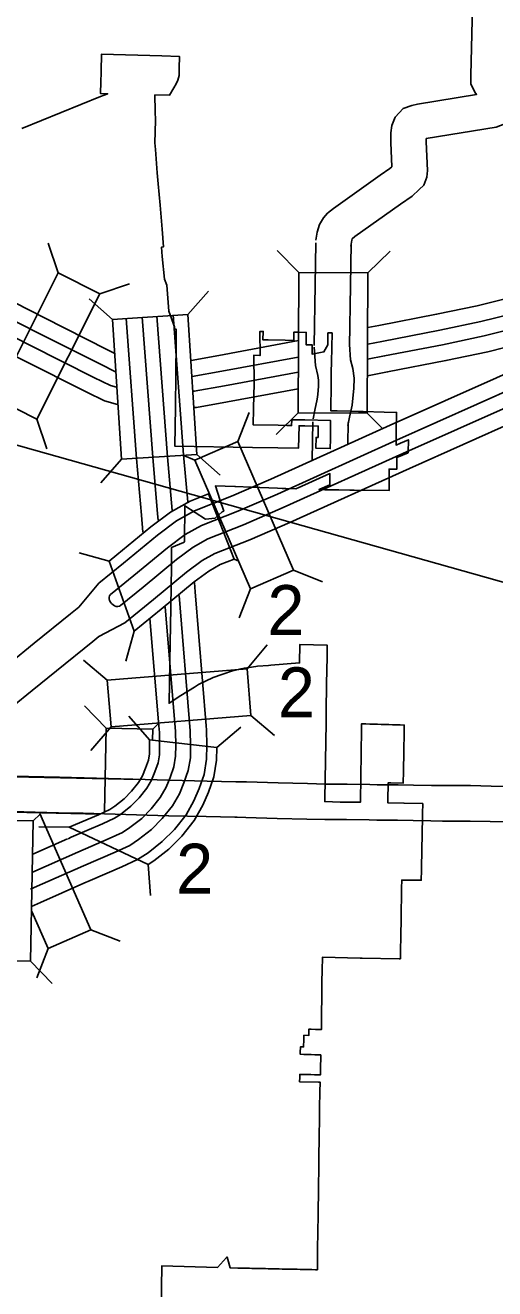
# Model space of a CAD drawing. Extents: x 535214 to 694517, y 381272 to 484355.
# Drawn here: x 547771 to 549760, y 458296 to 463649 of the extents above; entities that cross this region are included whole.
import ezdxf

# ---------------------------------------------------------------- set-up
doc = ezdxf.new("R2010")
doc.units = 0
for name, color, linetype in [('1', 7, 'Continuous'), ('Level 10', 7, 'Continuous'), ('Level 11', 7, 'Continuous'), ('Level 15', 7, 'Continuous'), ('Level 19', 7, 'Continuous'), ('Level 20', 7, 'Continuous'), ('Level 6', 7, 'Continuous')]:
    doc.layers.add(name, color=color, linetype=linetype)

msp = doc.modelspace()

# ---------------------------------------------------------------- linework, layer by layer
at = {"layer": '1'}
msp.add_line((546782.5, 462138.9), (567784.7, 456216.2), dxfattribs=at)
at = {"layer": 'Level 10'}
for p, q in [((548382.3, 460450.2), (548019.6, 460460.4)), ((548378.1, 460300.3), (548015.4, 460310.4))]:
    msp.add_line(p, q, dxfattribs=at)
for points in [[(548994.2, 462291.6), (548998.3, 462549)], [(549144.2, 462289.2), (549148.3, 462546.6)], [(548990.3, 461981.8), (548997.4, 462018.5), (549007.4, 462064.3), (549009.7, 462084), (549012.6, 462119.6), (549013.6, 462145.8), (549010.9, 462165.1), (549000, 462207.5), (548994.4, 462285)], [(549137.6, 461953.5), (549144.3, 461988.3), (549155.5, 462039.6), (549158.9, 462069.1), (549162.4, 462110.6), (549164, 462153.5), (549158.3, 462194.2), (549148.7, 462231.8), (549144, 462295.9)], [(548989, 461968.9), (548986.4, 461806.4)], [(549139, 461966.5), (549137.5, 461875.6)], [(548019.3, 460460.4), (547915, 460462.9), (547717.7, 460467.9), (547627.7, 460469.3), (547565.2, 460470.2), (547553.5, 460470.4), (547486.8, 460471.9), (547444.2, 460472.9), (547418.4, 460473.9), (547374, 460475.4), (547234.3, 460480.4), (547164.2, 460482.9), (547156.4, 460483.1), (547157.8, 460482.7)], [(547369.6, 460471.9), (547718.3, 460464.4), (548256.7, 460454.1)], [(549866.8, 460423.1), (549744.3, 460425.7), (549657.1, 460427.6), (549595.8, 460427.6), (549540.6, 460427.7), (549538.8, 460427.6), (549492, 460428.8), (549415.8, 460429.8), (549350.3, 460431), (549304, 460431.4), (549261.8, 460431.6), (549231, 460432.1), (549134.4, 460434), (549124.3, 460434.2), (549042.2, 460434.5), (548967.1, 460436.1), (548841.8, 460438.9), (548708.6, 460443), (548672.7, 460443.6), (548663.4, 460444), (548540.9, 460446.6), (548381.9, 460450.2)], [(548015.7, 460310.4), (547911.3, 460312.9), (547714.6, 460317.9), (547625.4, 460319.3), (547562.9, 460320.2), (547550.7, 460320.4), (547483.4, 460321.9), (547439.6, 460322.9), (547412.9, 460324), (547368.8, 460325.5), (547229, 460330.5), (547159.1, 460332.9), (547129.5, 460333.9), (547110.1, 460340.4)], [(547126.6, 460327.1), (547715.2, 460314.5), (548088.5, 460307.3)], [(549863, 460273.2), (549741.1, 460275.8), (549655.4, 460277.6), (549595.8, 460277.6), (549542.1, 460277.7), (549538.4, 460277.6), (549489.1, 460278.9), (549413.5, 460279.8), (549348.3, 460281), (549303, 460281.4), (549260.3, 460281.6), (549228.4, 460282.1), (549131.7, 460284.1), (549122.8, 460284.2), (549040.2, 460284.5), (548963.8, 460286.2), (548837.8, 460289), (548705.1, 460293.1), (548668.5, 460293.7), (548658.8, 460294.1), (548537.6, 460296.7), (548378.5, 460300.3)]]:
    msp.add_lwpolyline(points, dxfattribs=at)
at = {"layer": 'Level 11'}
for points in [[(549002.3, 462738.5), (549007.9, 462771.9), (549017, 462804.1), (549034.3, 462833.5), (549050.6, 462852.3), (549076.5, 462873.1), (549274.5, 463013.4), (549316, 463042.7), (549323.9, 463049.8), (549319.7, 463152.2), (549320, 463193.6), (549323.6, 463224.1), (549338.2, 463259.5), (549372.3, 463295.6), (549408.1, 463308.6), (549433.2, 463314.9), (549683, 463356), (549675.8, 463366), (549658.2, 463400.8), (549658.9, 463437.2), (549683.6, 464485.7)], [(549150.1, 462713.3), (549154.5, 462738.9), (549156.1, 462744.6), (549166.9, 462753.3), (549361.1, 462890.9), (549409.9, 462925.3), (549440.3, 462952.9), (549459.9, 462971), (549471.9, 463005.8), (549474.6, 463034.2), (549469.7, 463154.7), (549469.8, 463168.9), (549765.4, 463217.5), (549802.7, 463231.1), (549836.7, 463251.6), (549854.7, 463278.5), (549887.4, 463334.7), (549849.1, 463391.5), (549829.7, 463413.1), (549810.3, 463435.9), (549809, 463437.7), (549831.6, 464398.2)], [(548998.3, 462549), (549001.2, 462727.1)], [(549148.3, 462546.6), (549151.2, 462724.7)]]:
    msp.add_lwpolyline(points, dxfattribs=at)
at = {"layer": 'Level 15'}
for points in [[(548562.9, 461621.7), (548645.1, 461654.2), (548810.9, 461725.9), (549316.1, 461954.3), (549999.3, 462258.7), (550500.7, 462484.6), (550868, 462651.2), (551274.6, 462835.7), (551650, 463001.7), (551926.9, 463130.7), (552279.7, 463296.2), (552622.9, 463457.5), (552976.7, 463626.4), (553227, 463752.4), (553529.4, 463902.7)], [(548132.1, 461237), (548230.4, 461317.2), (548372.8, 461434.8), (548448.5, 461491), (548517.7, 461530), (548671.4, 461590.6), (548838.8, 461663), (549344.2, 461891.6), (550027.4, 462195.9), (550529, 462422), (550896.4, 462588.6), (551302.7, 462773), (551678.5, 462939.1), (551956, 463068.4), (552309, 463233.9), (552652.4, 463395.4), (553006.9, 463564.7), (553257.7, 463690.9), (553560, 463841.1)], [(548174.7, 461191.1), (548270.1, 461268.9), (548411.4, 461385.6), (548482.6, 461438.5), (548544.6, 461473.4), (548695.3, 461532.9), (548864, 461605.9), (549369.8, 461834.5), (550053, 462138.9), (550554.7, 462365), (550922.2, 462531.6), (551328.3, 462716), (551704.3, 462882.2), (551982.5, 463011.8), (552335.5, 463177.4), (552679.1, 463338.9), (553034.4, 463508.6), (553285.7, 463635), (553587.8, 463785.1)], [(548192.5, 461116.8), (548313.7, 461215.8), (548453.8, 461331.4), (548520.1, 461380.7), (548574.2, 461411.2), (548721.5, 461469.3), (548891.8, 461543), (549398, 461771.8), (550081.1, 462076.2), (550583.1, 462302.4), (550950.6, 462469), (551356.4, 462653.2), (551732.7, 462819.6), (552011.6, 462949.5), (552364.7, 463115.1), (552708.6, 463276.7), (553064.7, 463446.9), (553316.4, 463573.5), (553618.4, 463723.6)], [(548082.3, 461285), (548186.8, 461370.4), (548330.4, 461488.9), (548411, 461548.7), (548488, 461592.2), (548562.9, 461621.7)], [(547997.1, 461183.2), (548082.3, 461285)], [(547380.7, 460667.8), (547553.9, 460819.8), (547619.7, 460877.1), (547705, 460946.5), (547808.7, 461030.9), (547962.4, 461155), (547997.1, 461183.2)], [(548082.7, 461059.5), (548192.5, 461116.8)], [(547477.9, 460553.5), (547651.2, 460705.6), (547716.3, 460762.3), (547799.6, 460830.1), (547903.2, 460914.3), (548057, 461038.5), (548082.7, 461059.5)]]:
    msp.add_lwpolyline(points, dxfattribs=at)
msp.add_ellipse((548153.1, 461214.3), major_axis=(-21.3, 22.9), ratio=0.733949, start_param=0, end_param=3.141593, dxfattribs=at)
at = {"layer": 'Level 19'}
for points in [[(549222.2, 462368.2), (549268.1, 462376.8), (549513.2, 462424.3), (549685.3, 462460.4), (549815.9, 462493.3), (549962.3, 462537.7), (550092, 462586.4), (550342.3, 462700), (550645.6, 462843.1)], [(546870, 462738.3), (547131.8, 462710.4), (547182.4, 462701.5), (547240.5, 462683.4), (547297, 462665.7), (547358.4, 462644.4), (547412.5, 462621.2), (547497.8, 462583.9), (547662.1, 462505.5), (547848.7, 462410.2), (548119.5, 462274.2), (548147.9, 462260.4)], [(549222.4, 462298.2), (549281, 462309.3), (549526.8, 462356.9), (549700.7, 462393.4), (549834.3, 462427), (549984.4, 462472.6), (550118.3, 462522.8), (550371.2, 462637.6), (550648.8, 462768.6)], [(549220.1, 462164.3), (549305.7, 462180.4), (549552.7, 462228.3), (549730.2, 462265.5), (549869.4, 462300.5), (550026.6, 462348.2), (550168.5, 462401.5), (550426.3, 462518.5), (550872.7, 462729.1)], [(549220.4, 462234.3), (549292.8, 462247.9), (549539.1, 462295.7), (549714.8, 462332.5), (549851, 462366.8), (550004.5, 462413.3), (550142.2, 462465), (550397.4, 462580.9), (550651.4, 462700.7)], [(546864.1, 462669.8), (547122.2, 462642.3), (547166.1, 462634.5), (547220, 462617.8), (547275.5, 462600.4), (547333.5, 462580.3), (547385.1, 462558.1), (547469.2, 462521.3), (547631.7, 462443.9), (547817.6, 462348.8), (548089, 462212.6), (548153.5, 462181.3), (548154.7, 462180.9)], [(546858.3, 462607.6), (547113.4, 462580.4), (547151.4, 462573.7), (547201.4, 462558.1), (547255.9, 462541.1), (547310.9, 462522), (547360.3, 462500.7), (547443.2, 462464.5), (547604, 462387.8), (547789.4, 462293.1), (548061.4, 462156.6), (548131, 462122.7), (548157.2, 462115.2)], [(546846.9, 462539.7), (547103.8, 462512.3), (547135.1, 462506.7), (547181, 462492.5), (547234.4, 462475.8), (547286, 462457.8), (547332.9, 462437.6), (547414.7, 462401.9), (547573.5, 462326.2), (547758.3, 462231.8), (548030.9, 462094.9), (548106.4, 462058.2), (548162, 462042.3)], [(548333.6, 461552.3), (548331.4, 461579.6), (548310.8, 461818.8), (548266.3, 462412.1)], [(548373.4, 461820.3), (548328.6, 462416.8)], [(548458.8, 461629.5), (548441.6, 461829.4), (548397.2, 462422.2)], [(548268.9, 461500.7), (548262.9, 461573.8), (548242.3, 461813.3), (548197.8, 462406.9)], [(548472.9, 462229.2), (548591.1, 462250.4), (548929, 462313)], [(548477.5, 462160.2), (548603.4, 462182.8), (548927.2, 462242.8)], [(548481.4, 462097.7), (548486.1, 462098.2), (548614.6, 462121.3), (548927.3, 462179.2)], [(548485.3, 462028.9), (548496.2, 462030.2), (548627, 462053.6), (548927.1, 462109.2)], [(548393, 461592.8), (548373.4, 461820.3)], [(548537, 460681.5), (548490.4, 461248.6), (548487.2, 461287.5)], [(547793.3, 459989.6), (547807.6, 459995.9), (548017.8, 460088.3), (548151.9, 460145.9), (548213, 460174.5), (548250.8, 460199.2), (548305.4, 460242.1), (548351.1, 460288), (548394.7, 460342.6), (548423.5, 460393.2), (548442.7, 460440), (548461, 460492), (548470, 460546), (548471.2, 460599), (548469.8, 460659.7), (548422.7, 461233.4)], [(547797.7, 460059.8), (547992.9, 460145.7), (548126.3, 460203), (548182.5, 460229.2), (548214.3, 460250), (548263.8, 460288.9), (548304.4, 460329.7), (548342.8, 460377.8), (548367.2, 460420.6), (548384.3, 460462.2), (548400.3, 460507.6), (548407.6, 460551.8), (548408.7, 460598.9), (548407.3, 460656.4), (548363.9, 461185.6)], [(548336.3, 460681), (548299, 461135.6)], [(547951.8, 460202.7), (547965.5, 460208.7), (548098.2, 460265.7), (548149, 460289.4), (548174.2, 460305.9), (548218, 460340.4), (548253, 460375.5), (548285.8, 460416.5), (548305.3, 460450.8), (548320.1, 460486.7), (548333.4, 460524.7), (548339, 460558.3), (548339.9, 460598.9), (548338.7, 460652.7), (548336.3, 460681)], [(548018.9, 460013.7), (548045.2, 460025.3), (548180, 460083.2), (548246.6, 460114.3), (548290.9, 460143.3), (548351.2, 460190.7), (548402.4, 460242.2), (548451.8, 460303.9), (548485.4, 460363), (548507, 460415.5), (548527.9, 460474.8), (548538.6, 460539.5), (548540, 460599), (548538.5, 460663.3), (548537, 460681.3)], [(547802.6, 460137.1), (547949.6, 460201.7)], [(547796.3, 459915.7), (547835.4, 459933), (548018.9, 460013.7)]]:
    msp.add_lwpolyline(points, dxfattribs=at)
at = {"layer": 'Level 20'}
for p, q in [((547909.5, 462600.1), (547868, 462725.3)), ((548930.4, 462601.4), (548837.6, 462695.2)), ((549222.7, 462599.7), (549316.6, 462692.5)), ((548930.4, 462601.4), (548927.1, 462007.4)), ((549222.7, 462599.7), (548930.4, 462601.4)), ((548930.4, 462601.4), (548930.4, 462601.4)), ((549222.7, 462599.7), (549219.4, 462005.7)), ((548086.5, 462511.2), (548211.8, 462552.8)), ((548460, 462423.4), (548547.1, 462522.5)), ((548140.2, 462402.9), (548041, 462490.1)), ((548460, 462423.4), (548140.2, 462402.9)), ((548460, 462423.4), (548498, 461830.6)), ((548140.2, 462402.9), (548178.2, 461810.1)), ((547820, 461980.4), (547861.5, 461855.1)), ((548671.3, 461885.2), (548719.9, 462007.9)), ((548927.1, 462007.4), (548833.3, 461914.5)), ((548927.1, 462007.4), (549219.4, 462005.7)), ((549219.4, 462005.7), (549285.4, 461938.9)), ((548671.3, 461885.2), (548489.6, 461806.6)), ((548907.1, 461340), (548671.3, 461885.2)), ((548178.2, 461810.1), (548498, 461830.6)), ((548489.6, 461806.6), (548441.8, 461825.5)), ((548498, 461830.6), (548597.1, 461743.5)), ((548178.2, 461810.1), (548091, 461711)), ((548489.6, 461806.6), (548725.4, 461261.4)), ((548548.9, 461669), (548546.4, 461663.4)), ((548546.4, 461663.4), (548655.5, 461387.1)), ((547998.6, 461413.2), (548126, 461378.7)), ((548126, 461378.7), (548231.6, 461081.4)), ((548675.1, 461379), (548655.5, 461387.1)), ((548725.4, 461261.4), (548907.1, 461340)), ((548907.1, 461340), (549029.9, 461291.4)), ((548725.4, 461261.4), (548676.8, 461138.7)), ((548196.3, 460954.2), (548231.6, 461081.4)), ((548710.2, 460922.7), (548795.6, 461023.4)), ((548118.2, 460874.1), (548017.6, 460959.5)), ((548710.2, 460922.7), (548118.2, 460874.1)), ((548726.4, 460725.4), (548710.2, 460922.7)), ((548118.2, 460874.1), (548134.4, 460676.8)), ((548112.9, 460670.9), (548021.4, 460766.1)), ((548134.4, 460676.8), (548726.4, 460725.4)), ((548210, 460721.8), (548297, 460621.6)), ((548726.4, 460725.4), (548827.1, 460640)), ((548134.4, 460676.8), (548049, 460576.1)), ((548112.9, 460670.9), (548106.1, 460316.2)), ((548310.9, 460667.1), (548112.9, 460670.9)), ((548310, 460619.9), (548310.9, 460667.1)), ((548310.9, 460667.1), (548336.9, 460692.2)), ((548683.7, 460674.6), (548582, 460588.9)), ((548582, 460588.9), (548297, 460621.6)), ((547804.6, 460278.1), (547606.6, 460281.8)), ((547793.4, 459684.2), (547804.6, 460278.1)), ((547804.6, 460278.1), (547833.9, 460306.3)), ((548049, 459816.8), (547832.3, 460309.5)), ((547827.4, 460253.6), (547957.2, 460251.3)), ((547957.2, 460251.3), (548291, 460094.1)), ((548300.5, 459962.2), (548291, 460094.1)), ((547798.6, 459894.2), (547867.7, 459737)), ((547867.7, 459737), (548049, 459816.8)), ((548049, 459816.8), (548172, 459768.9)), ((547867.7, 459737), (547819.8, 459614)), ((547595.4, 459687.9), (547793.4, 459684.2)), ((547793.4, 459684.2), (547884.9, 459589.1))]:
    msp.add_line(p, q, dxfattribs=at)
msp.add_lwpolyline([(547820, 461980.4), (548086.5, 462511.2), (547909.5, 462600.1), (547643, 462069.2)], close=True, dxfattribs=at)
for points in [[(548126, 461378.7), (548158.4, 461405.1), (548302.8, 461524.2), (548386.5, 461586.4), (548468.7, 461632.8), (548546.4, 461663.4)], [(548231.6, 461081.4), (548346.8, 461175.4), (548486, 461290.3), (548548.6, 461336.8), (548596.8, 461363.9), (548655.5, 461387.1)], [(547957.2, 460251.3), (548080.8, 460304.4), (548128.3, 460326.6), (548149.4, 460340.4), (548189.8, 460372.1), (548221.3, 460403.8), (548250.5, 460440.4), (548267.1, 460469.5), (548280.4, 460501.8), (548292.2, 460535.3), (548296.6, 460562.3), (548297.5, 460598.9), (548297, 460621.6)], [(548291.5, 460093.2), (548315.6, 460108.9), (548379.3, 460159), (548434, 460214), (548486.9, 460280.1), (548523.5, 460344.4), (548546.5, 460400.4), (548569, 460464.2), (548580.8, 460535.5), (548582, 460588.9)]]:
    msp.add_lwpolyline(points, dxfattribs=at)
at = {"layer": 'Level 6'}
for points in [[(547756, 463211.8), (548089.4, 463346.4), (548119.7, 463358.5), (548089.6, 463359.4), (548089.7, 463364.2), (548089.7, 463364.4), (548089.7, 463365.9), (548090.6, 463403.6), (548091.8, 463454.2), (548093.5, 463526), (548348.9, 463518.8), (548423.9, 463516.7), (548423.2, 463466.7), (548422.7, 463436), (548416.7, 463415.6), (548410, 463400.7), (548400.3, 463383.2), (548381.6, 463353.1), (548381.4, 463352.6), (548319.8, 463354), (548321, 463284.8), (548322.1, 463245)], [(548322.1, 463245), (548319.9, 463150.1), (548322, 463121.9), (548330.1, 463024.1), (548333.8, 462976.7), (548341.6, 462887.3), (548350, 462785.1), (548356.2, 462709.7), (548347.9, 462709.1), (548350.8, 462669.2), (548361, 462573.7), (548369.7, 462548), (548379.1, 462437.1), (548403.1, 462371.1), (548403.5, 462361.5), (548410.5, 462361.3), (548410.5, 462354.9), (548410, 462307.7), (548407.4, 462031.3), (548403.6, 461866.3), (548733.6, 461859.9), (548733.6, 461860.4), (548840.3, 461859), (548928.5, 461857.8), (548930.7, 461952.4), (548951.9, 461952), (548952.4, 461952), (548955.2, 461951.9), (549009, 461950.8), (549012.3, 461950.8), (549012.2, 461938.6), (549011.3, 461902.8), (549003, 461903), (549002.3, 461856.9), (549062.9, 461855.3), (549063.4, 461895.3), (549063.5, 461901.5), (549064.1, 461937.2), (549064, 461949.7), (549064.2, 461951.7), (549064.2, 461955), (549064.6, 461974.4), (548955.7, 461976.7), (548899.6, 461977.8), (548899, 461953.1), (548878.7, 461953.5), (548842.5, 461954.3), (548736.2, 461956.4), (548737.4, 462023.7), (548737.4, 462026.7), (548739.8, 462130.6), (548738.6, 462250.9), (548764.9, 462249.4), (548765.5, 462249.4), (548764.8, 462352), (548778.7, 462351.7), (548777, 462316.5), (548799.6, 462316), (548872.4, 462314.4), (548908.6, 462313.6), (548908.7, 462349.1), (548927.7, 462348.7), (548961.2, 462347.9), (548961.2, 462347.4), (548960.2, 462295.4), (548986.6, 462295), (548985.9, 462255.9), (549036.2, 462264.9), (549052.1, 462294.7), (549053, 462345.6), (549070.6, 462345.2), (549068.3, 462221.2), (549067.2, 462180.8), (549066.9, 462146.9), (549066.4, 462098.2), (549066.1, 462080.1), (549066, 462065.7), (549065.9, 462059.4), (549065.6, 462040.7), (549065.4, 462022), (549065.3, 462015.7), (549068.6, 462015.6), (549071.6, 462015.6), (549092.1, 462014.9), (549152.8, 462013.7), (549182.2, 462013), (549201.8, 462012.5), (549290.8, 462010.3), (549343.6, 462009), (549342.6, 461930.7), (549341.8, 461870.5), (549360.7, 461878.6), (549394.1, 461893.1), (549393, 461838.7), (549393, 461838.1), (549345.3, 461817.3), (549345, 461768.4), (549316.3, 461768.6), (549312.3, 461768.6), (549312.6, 461738)], [(549312.6, 461738), (549313.2, 461681.7), (549313.2, 461678.1), (549163.7, 461679.5), (549145.2, 461679.6), (549098.7, 461680.2), (549060.9, 461680.6), (549059, 461680.7), (549039.2, 461681.3), (549015.7, 461682), (549018.4, 461683.2), (549061.1, 461701.5), (549061.7, 461749.6), (548926.6, 461688.8), (548920.3, 461686.3), (548916.9, 461684.9), (548874.3, 461686.2), (548858.9, 461686.7), (548839.5, 461687.4), (548727.9, 461692), (548661.1, 461694.7), (548658.9, 461694.8), (548576, 461697.1), (548595.2, 461639.3), (548611.3, 461590.6), (548604.8, 461587.4), (548575.4, 461561.3), (548534.5, 461557), (548447.3, 461613), (548444.8, 461460.6), (548443.3, 461459.6), (548441.3, 461458.2), (548390.4, 461436.7), (548389.8, 461367), (548389.8, 461356.4), (548385.4, 461100.8), (548384.3, 461037), (548379.8, 460776.6), (548430.4, 460809.5), (548487.8, 460845.4), (548504.6, 460855.9), (548566.6, 460885.7), (548643.8, 460911.9), (548683.9, 460921.9), (548699.4, 460925.8), (548718.6, 460928.3), (548747.4, 460932.2), (548754.4, 460933.1), (548801.9, 460937), (548810.8, 460937.8), (548932.6, 460947.2), (548933.7, 461025.1), (549050.4, 461022.4), (549049.4, 460956.6), (549049, 460931.7), (549045.9, 460755.7), (549044.9, 460693.6), (549044.9, 460693.2), (549039.9, 460372.2), (549039.6, 460359.9), (549105, 460358), (549165.7, 460357.5), (549190.6, 460357.2), (549190.7, 460366.9), (549191.1, 460387.1), (549191.3, 460404), (549191.8, 460420.5), (549192, 460437.7), (549192.3, 460454.7), (549192.5, 460471.8), (549192.7, 460488.8), (549193, 460505.7), (549193.2, 460522.7), (549193.3, 460527.4), (549193.5, 460539.6), (549193.7, 460556.7), (549194, 460573.8), (549194.3, 460590.8), (549194.5, 460607.7), (549194.8, 460624.8), (549195.2, 460645), (549195.4, 460657.4), (549195.9, 460689.6), (549213.5, 460689.1), (549229.9, 460688.6), (549246.1, 460688.1), (549262.4, 460687.7), (549278.6, 460687.2), (549294.8, 460686.7), (549311.2, 460686.2), (549327.2, 460685.8), (549343.4, 460685.3), (549359.7, 460684.8), (549376.4, 460684.3), (549375.9, 460652.2), (549375.7, 460639.8), (549375.4, 460621.2), (549375.1, 460604.9), (549374.9, 460588.2), (549374.6, 460571.8)], [(549374.6, 460571.8), (549374.3, 460555.1), (549374.1, 460538.7), (549373.8, 460522.2), (549373.5, 460505.7), (549373.3, 460489.2), (549372.5, 460438.6), (549319.7, 460439.8), (549308.7, 460440.1), (549307.5, 460364.5), (549307.4, 460354.6), (549374.6, 460353.3), (549375.6, 460353.3), (549454.9, 460351.8), (549454.9, 460341.1), (549454.4, 460320.7), (549454, 460302.4), (549453.7, 460285.3), (549453.3, 460268), (549452.9, 460249.8), (549452.5, 460232.5), (549452.2, 460215), (549451.8, 460197.5), (549451.4, 460179.6), (549451.3, 460173.7), (549451.1, 460162.2), (549450.7, 460143.6), (549450.3, 460126.2), (549449.9, 460107.6), (549449.5, 460090.8), (549449.1, 460069.6), (549448.2, 460026.5), (549446.2, 460026.6), (549396.6, 460027.1), (549365.9, 460027.4), (549365.3, 459993.5), (549365, 459991.8), (549365, 459981), (549364.7, 459963.6), (549364.4, 459947.3), (549364.3, 459940.5), (549364.1, 459931.3), (549364, 459923.1), (549364, 459915.3), (549363.8, 459899.1), (549363.5, 459883.4), (549363.2, 459867.3), (549363, 459851.7), (549362.7, 459835.7), (549362.5, 459819.9), (549362.2, 459803.7), (549361.9, 459788.2), (549361.7, 459771.9), (549361.2, 459745.4), (549360.6, 459703.9), (549360.5, 459700), (549360.1, 459693.9), (549359.6, 459694), (549355.1, 459694), (549197.5, 459696.3), (549190.2, 459696.6), (549029.5, 459700.4), (549029.5, 459699), (549028.5, 459646.4), (549027.8, 459596.4), (549027.7, 459583.9), (549026.9, 459523.9), (549026.7, 459511.4), (549026.3, 459481.4), (549025.9, 459451.4), (549025.8, 459438.9), (549025.2, 459394.1), (549024, 459394.2), (549017.7, 459394.4), (548999.8, 459395), (548982.3, 459395.6), (548972.7, 459395.9), (548972.7, 459394.8), (548972.4, 459369.6), (548951.2, 459370.3), (548950.8, 459352.1), (548950.2, 459320.4), (548936.6, 459320.8), (548936, 459297.6), (548935.8, 459289.5), (548951.3, 459289.1), (548966.8, 459288.6), (548982.3, 459288.2), (548997.8, 459287.7), (549015.4, 459287.2), (549022, 459287), (549022.9, 459287), (549022.5, 459271.9), (549021.8, 459239.5), (549021.5, 459227), (549020.9, 459202), (549020.4, 459202), (549013.4, 459202.2), (548995.8, 459202.7), (548980.3, 459203.2)], [(548980.3, 459203.2), (548964.8, 459203.6), (548949.3, 459204.1), (548933.8, 459204.5), (548933.4, 459189.5), (548933, 459174.5), (548933, 459173.3), (549012.7, 459171), (549019.8, 459170.8), (549020.2, 459170.7), (549020.1, 459167.3), (549019.2, 459134.8), (549017.5, 459058.3), (549017, 459037.5), (549015.8, 458921.4), (549015.1, 458869.2), (549014.4, 458821.4), (549013, 458716.8), (549012.8, 458704), (549011.8, 458629.3), (549011.8, 458624.3), (549011.2, 458585), (549010.9, 458560.1), (549010.6, 458541.8), (549009.5, 458459.3), (549008.4, 458376.8), (549000.9, 458376.9), (548984.7, 458377.3), (548972.2, 458377.5), (548959.7, 458377.8), (548947.2, 458378), (548934.7, 458378.3), (548922.2, 458378.5), (548909.7, 458378.7), (548897.2, 458379), (548884.6, 458379.2), (548872.1, 458379.5), (548859.6, 458379.7), (548847.1, 458380), (548830.1, 458380.3), (548814.8, 458380.7), (548800.9, 458381), (548800.1, 458381), (548788.4, 458381.3), (548786.5, 458381.3), (548779.5, 458381.5), (548777.2, 458381.5), (548772.5, 458381.6), (548765.6, 458381.8), (548757.9, 458382), (548754.3, 458382.1), (548743.8, 458382.3), (548742.9, 458382.3), (548731.6, 458382.6), (548730, 458382.6), (548720.3, 458382.9), (548716.4, 458382.9), (548708.9, 458383.1), (548702.7, 458383.3), (548697.8, 458383.4), (548688.7, 458383.6), (548686.1, 458383.6), (548673.8, 458383.9), (548671.2, 458384), (548638.9, 458384.7), (548628.5, 458419.9), (548625.5, 458430), (548623.9, 458428.4), (548584.7, 458386), (548348.6, 458392.6), (548341, 457837.9)]]:
    msp.add_lwpolyline(points, dxfattribs=at)

# ---------------------------------------------------------------- texts
at = {"layer": 'Level 20'}
for p in [(548796.6, 461066), (548840.8, 460717.4), (548409.8, 459970.4)]:
    msp.add_text('2', height=211.2, dxfattribs=at).set_placement(p)

doc.saveas('drawing.dxf')
